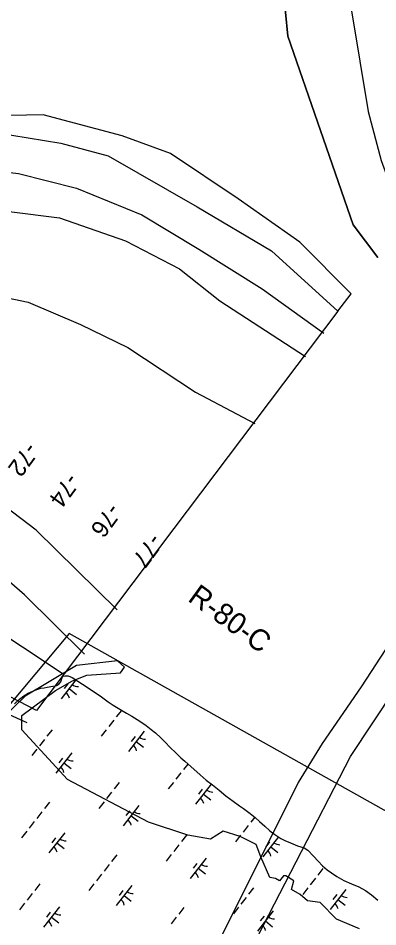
# Model space of a CAD drawing. Extents: x 3896831 to 3918110, y 171006 to 193349.
# Drawn here: x 3907102 to 3907802, y 176349 to 178119 of the extents above; entities that cross this region are included whole.
import ezdxf

# ---------------------------------------------------------------- set-up
doc = ezdxf.new("R2010")
doc.units = 0
for name, color, linetype in [('V-RIVR-EDGE', 7, 'Continuous'), ('V-RIVR-RANG', 7, 'Continuous'), ('V-RIVR-RANG-IDEN', 7, 'Continuous'), ('V-RRAP-FSHR', 7, 'Continuous'), ('V-TOPO-DPTH', 7, 'Continuous'), ('V-TOPO-MAJR', 7, 'Continuous'), ('V-TOPO-MINR', 7, 'Continuous'), ('V-UTIL-LINE', 7, 'Continuous'), ('V-WETL-SWMP', 7, 'Continuous')]:
    doc.layers.add(name, color=color, linetype=linetype)

msp = doc.modelspace()

# ---------------------------------------------------------------- linework, layer by layer
at = {"layer": 'V-RIVR-EDGE'}
msp.add_lwpolyline([(3907767, 176345.3), (3907721.7, 176364), (3907690.4, 176396.8), (3907665.4, 176400), (3907651.4, 176412.5), (3907634.2, 176421.8), (3907638.9, 176439), (3907623.2, 176448.4), (3907618.5, 176448.4), (3907610.7, 176439), (3907602.9, 176443.7), (3907592, 176445.3), (3907574.8, 176485.9), (3907565.4, 176509.4), (3907534.1, 176525), (3907501.3, 176535.9), (3907476.3, 176520.3), (3907432.5, 176528.1), (3907355.9, 176553.1), (3907198.1, 176636), (3907109, 176732.9), (3907109, 176761), (3907174.6, 176809.5), (3907207.4, 176828.2), (3907235.6, 176839.2), (3907301.2, 176843.9), (3907309, 176854.8), (3907295, 176867.3), (3907215.3, 176857.9), (3907115.2, 176798.5), (3907038.6, 176725.1)], dxfattribs=at)
at = {"layer": 'V-RRAP-FSHR'}
msp.add_lwpolyline([(3908001.4, 176472.2), (3907201.3, 176920.5), (3906173.6, 175695), (3905294, 175071.7), (3904787.4, 174237.7)], dxfattribs=at)
at = {"layer": 'V-TOPO-DPTH'}
for q in [(3907750.4, 177581.8), (3907137.2, 176770.5)]:
    msp.add_line((3907724.8, 177547.9), q, dxfattribs=at)
for points in [[(3907802.4, 177652.7), (3907754.6, 177716.3), (3907627.2, 178083.7), (3907599.9, 178364.7), (3907615.4, 178532.3), (3907646.9, 178623.4), (3907701.3, 178701.9)], [(3907701.3, 178701.9), (3907646.9, 178623.4), (3907615.4, 178532.3), (3907599.9, 178364.7), (3907627.2, 178083.7), (3907754.6, 177716.3), (3907802.4, 177652.7)], [(3907750.4, 177581.8), (3907650.6, 177682.4), (3907530.5, 177766.6), (3907398.8, 177854.9), (3907304.2, 177889.3), (3907150.4, 177930.5), (3907051.9, 177928.3)], [(3907750.4, 177581.8), (3907650.6, 177682.4), (3907530.5, 177766.6), (3907398.8, 177854.9), (3907304.2, 177889.3), (3907150.4, 177930.5), (3907051.9, 177928.3)], [(3907137.2, 176770.5), (3907017.8, 176832.2), (3906783.3, 176956), (3906642.5, 177046.4), (3906576.4, 177130.2), (3906534.8, 177214.7), (3906507.5, 177292), (3906536, 177389.4), (3906584, 177547.5), (3906616.4, 177594), (3906701.7, 177702.8), (3906783.4, 177786.6), (3906899.5, 177863.4), (3907056.7, 177895.9), (3907184.6, 177875.5), (3907277.1, 177850.9), (3907450.4, 177751.1), (3907595.1, 177665.6), (3907724.8, 177547.9)], [(3907137.2, 176770.5), (3907017.8, 176832.2), (3906783.3, 176956), (3906642.5, 177046.4), (3906576.4, 177130.2), (3906534.8, 177214.7), (3906507.5, 177292), (3906536, 177389.4), (3906584, 177547.5), (3906616.4, 177594), (3906701.7, 177702.8), (3906783.4, 177786.6), (3906899.5, 177863.4), (3907056.7, 177895.9), (3907184.6, 177875.5), (3907277.1, 177850.9), (3907450.4, 177751.1), (3907595.1, 177665.6), (3907724.8, 177547.9)], [(3907037.7, 176783.3), (3907118.6, 176747.2), (3907118.6, 176747.2), (3907118.6, 176747.2)], [(3907037.7, 176783.3), (3907118.6, 176747.2), (3907118.6, 176747.2), (3907118.6, 176747.2)]]:
    msp.add_lwpolyline(points, dxfattribs=at)
at = {"layer": 'V-TOPO-MAJR'}
msp.add_lwpolyline([(3907191.5, 176839.8), (3907028.4, 176947.6), (3906922, 177031), (3906808.2, 177120.2), (3906707.1, 177215.4), (3906631.8, 177282.4), (3906605.8, 177330.7), (3906587.8, 177368.9), (3906582.7, 177428.7), (3906610, 177499.2), (3906694.4, 177652.7), (3906753.3, 177702.4), (3906826.8, 177760.5), (3906911.4, 177802.1), (3906999.9, 177828.5), (3907102.2, 177816.3), (3907215.4, 177787.5), (3907342.6, 177735.7), (3907453.7, 177668.6), (3907577.2, 177591.8), (3907697.3, 177505.3)], dxfattribs=at)
at = {"layer": 'V-TOPO-MINR'}
for points in [[(3907701.3, 178701.9), (3907646.9, 178623.4), (3907615.4, 178532.3), (3907599.9, 178364.7), (3907627.2, 178083.7), (3907754.6, 177716.3), (3907802.4, 177652.7)], [(3907786.2, 178645.6), (3907752, 178569), (3907730.7, 178485.8), (3907721.7, 178357.1), (3907734.2, 178235.5), (3907783.8, 177937), (3907808.8, 177841.5), (3907835.6, 177768.6), (3907857.3, 177732.9)], [(3907750.4, 177581.8), (3907650.6, 177682.4), (3907530.5, 177766.6), (3907398.8, 177854.9), (3907304.2, 177889.3), (3907150.4, 177930.5), (3907051.9, 177928.3)], [(3907137.2, 176770.5), (3907017.8, 176832.2), (3906783.3, 176956), (3906642.5, 177046.4), (3906576.4, 177130.2), (3906534.8, 177214.7), (3906507.5, 177292), (3906536, 177389.4), (3906584, 177547.5), (3906616.4, 177594), (3906701.7, 177702.8), (3906783.4, 177786.6), (3906899.5, 177863.4), (3907056.7, 177895.9), (3907184.6, 177875.5), (3907277.1, 177850.9), (3907450.4, 177751.1), (3907595.1, 177665.6), (3907724.8, 177547.9)], [(3907231.3, 176880.4), (3907114.3, 176996.1), (3906997, 177096.1), (3906889.5, 177188.3), (3906684.2, 177349.2), (3906647.9, 177389.6), (3906632, 177410), (3906633.9, 177468.5), (3906687.8, 177578), (3906718.3, 177622), (3906750.7, 177668.5), (3906804.8, 177701.9), (3906892.9, 177732.7), (3906991.1, 177735.7), (3907084.3, 177742.5), (3907182.1, 177729.7), (3907310.7, 177684.9), (3907415.8, 177630.4), (3907494.9, 177568.4), (3907661.6, 177459.9)], [(3907294.8, 176966.5), (3907137.1, 177122), (3907016.4, 177212.6), (3906947.5, 177282.6), (3906881, 177350.7), (3906837.3, 177396.9), (3906829, 177447.4), (3906871.1, 177506.2), (3906934.4, 177556.4), (3906996, 177584), (3907052.5, 177579.7), (3907121.4, 177565.6), (3907222.9, 177522), (3907315.7, 177477.2), (3907447.1, 177390.2), (3907563.1, 177329.3)], [(3907037.7, 176783.3), (3907118.6, 176747.2), (3907118.6, 176747.2), (3907118.6, 176747.2)]]:
    msp.add_lwpolyline(points, dxfattribs=at)
at = {"layer": 'V-UTIL-LINE'}
for points in [[(3905549.4, 173652.6), (3906763.3, 174938.4), (3906949.5, 175133), (3906970.6, 175166.8), (3907325.9, 175860.5), (3907748.9, 176681), (3908142.2, 177273.2), (3908679.4, 178098), (3908869.7, 178381.4), (3908937.4, 178537.8), (3909170, 179117.3), (3909533.8, 179633.3), (3910092.1, 180424.3), (3910333.2, 180766.9), (3910760.4, 181291.4), (3910921.1, 181524), (3911225.6, 181951.2), (3911822, 182788.6), (3911961.6, 182987.4), (3912147.7, 183114.3), (3912722.9, 183841.8), (3913090.9, 184307.1), (3913848, 185258.8), (3914364, 185910.1)], [(3913133.2, 183520.4), (3913116.3, 183516.1), (3912989.4, 183516.1), (3912744.1, 183393.5), (3911902.4, 182441.8), (3910866.1, 181249.1), (3910603.9, 180953), (3910214.7, 180504.6), (3910138.6, 180390.4), (3909757.9, 179819.4), (3909457.6, 179366.9), (3909009.3, 178685.9), (3908785.1, 178351.7), (3908150.7, 177400.1), (3907770, 176816.4), (3907693.9, 176706.4), (3907647.3, 176630.3), (3907300.5, 175936.6), (3907025.6, 175369.8), (3906945.2, 175204.9), (3906416.5, 174650.8), (3905507.1, 173682.2)]]:
    msp.add_lwpolyline(points, dxfattribs=at)
at = {"layer": 'V-WETL-SWMP'}
for p, q in [((3907184.6, 176826.5), (3907187.6, 176835.1)), ((3907187.6, 176835.1), (3907188.7, 176836.9)), ((3907188.7, 176836.9), (3907188.9, 176837.1)), ((3907188.9, 176837.1), (3907193.6, 176838.2)), ((3907193.6, 176838.2), (3907199, 176838)), ((3907199, 176838), (3907206.8, 176834.9)), ((3907206.8, 176834.9), (3907226.8, 176821.9)), ((3907158.5, 176816), (3907169.6, 176817.8)), ((3907169.6, 176817.8), (3907176.6, 176819.2)), ((3907176.6, 176819.2), (3907181.5, 176822.6)), ((3907181.5, 176822.6), (3907184.6, 176826.5)), ((3907214.3, 176830), (3907185.6, 176793.4)), ((3907198.6, 176822.5), (3907191.2, 176813.1)), ((3907226.8, 176821.9), (3907253.7, 176804.4)), ((3907104.6, 176792.5), (3907113.1, 176799.3)), ((3907113.1, 176799.3), (3907121.3, 176804)), ((3907121.3, 176804), (3907130.3, 176808)), ((3907130.3, 176808), (3907139.9, 176811.9)), ((3907139.9, 176811.9), (3907146.1, 176813.8)), ((3907146.1, 176813.8), (3907152.1, 176814.9)), ((3907152.1, 176814.9), (3907158.5, 176816)), ((3907201, 176813.1), (3907215.2, 176802)), ((3907253.7, 176804.4), (3907264.4, 176796.9)), ((3907094.5, 176783.7), (3907104.6, 176792.5)), ((3907264.4, 176796.9), (3907276.9, 176787.6)), ((3907276.9, 176787.6), (3907286.6, 176781.2)), ((3907286.6, 176781.2), (3907299.7, 176773.2)), ((3907302.8, 176770.6), (3907293, 176758.1)), ((3907299.7, 176773.2), (3907313, 176765.5)), ((3907313, 176765.5), (3907322.9, 176759.6)), ((3907288, 176751.8), (3907278.2, 176739.2)), ((3907322.9, 176759.6), (3907333.4, 176752.9)), ((3907333.4, 176752.9), (3907342.8, 176747)), ((3907342.8, 176747), (3907350.9, 176741.6)), ((3907167.8, 176733), (3907157.9, 176720.4)), ((3907273.2, 176732.9), (3907263.3, 176720.3)), ((3907347.4, 176730.1), (3907316.5, 176690.8)), ((3907350.9, 176741.6), (3907361.1, 176733.6)), ((3907361.1, 176733.6), (3907369.2, 176726.8)), ((3907153, 176714.1), (3907143.1, 176701.5)), ((3907329.6, 176719.9), (3907322.2, 176710.5)), ((3907331.9, 176710.5), (3907346.1, 176699.4)), ((3907369.2, 176726.8), (3907380, 176717.3)), ((3907380, 176717.3), (3907388.4, 176709)), ((3907138.1, 176695.2), (3907128.3, 176682.6)), ((3907388.4, 176709), (3907397.8, 176698.7)), ((3907397.8, 176698.7), (3907408.8, 176687.8)), ((3907206, 176688.2), (3907175.1, 176648.8)), ((3907188.2, 176678), (3907180.8, 176668.5)), ((3907408.8, 176687.8), (3907418.8, 176678.5)), ((3907418.8, 176678.5), (3907426.4, 176671.8)), ((3907190.5, 176668.5), (3907204.7, 176657.4)), ((3907432.4, 176666.3), (3907423.9, 176655.4)), ((3907426.4, 176671.8), (3907432.7, 176666.1)), ((3907432.7, 176666.1), (3907443.7, 176656.6)), ((3907418.9, 176649.1), (3907409.1, 176636.6)), ((3907443.7, 176656.6), (3907456.2, 176645.5)), ((3907456.2, 176645.5), (3907468.3, 176635.1)), ((3907298.7, 176630.4), (3907288.8, 176617.8)), ((3907404.1, 176630.3), (3907394.3, 176617.7)), ((3907478, 176627.2), (3907447.4, 176588.2)), ((3907468.3, 176635.1), (3907480.1, 176625.6)), ((3907480.1, 176625.6), (3907493.1, 176615.3)), ((3907283.9, 176611.5), (3907274, 176598.9)), ((3907460.5, 176617.3), (3907453.1, 176607.9)), ((3907462.8, 176607.8), (3907477, 176596.7)), ((3907493.1, 176615.3), (3907506.2, 176604.7)), ((3907506.2, 176604.7), (3907520.4, 176593.8)), ((3907162.8, 176592), (3907153, 176579.4)), ((3907269.1, 176592.6), (3907259.2, 176580)), ((3907520.4, 176593.8), (3907533.2, 176585.1)), ((3907148, 176573.1), (3907138.2, 176560.5)), ((3907336.9, 176585.6), (3907306, 176546.2)), ((3907319.1, 176575.4), (3907311.7, 176565.9)), ((3907533.2, 176585.1), (3907540.8, 176579.4)), ((3907540.8, 176579.4), (3907553.8, 176570.1)), ((3907553.8, 176570.1), (3907563.3, 176562.1)), ((3907133.2, 176554.2), (3907123.3, 176541.6)), ((3907321.5, 176565.9), (3907335.6, 176554.8)), ((3907562.6, 176562.7), (3907554.8, 176552.8)), ((3907563.3, 176562.1), (3907572.2, 176554.4)), ((3907572.2, 176554.4), (3907582.1, 176545.1)), ((3907118.4, 176535.4), (3907108.5, 176522.8)), ((3907549.9, 176546.5), (3907540, 176533.9)), ((3907582.1, 176545.1), (3907592.3, 176536.3)), ((3907592.3, 176536.3), (3907601.5, 176528.8)), ((3907192.5, 176532.6), (3907161.7, 176493.3)), ((3907174.8, 176522.4), (3907167.4, 176513)), ((3907429.6, 176527.8), (3907419.7, 176515.2)), ((3907535.1, 176527.7), (3907525.2, 176515.1)), ((3907608.7, 176524.3), (3907578.3, 176485.6)), ((3907601.5, 176528.8), (3907613.3, 176521.4)), ((3907613.3, 176521.4), (3907621.4, 176517.5)), ((3907621.4, 176517.5), (3907632.1, 176512.9)), ((3907177.1, 176512.9), (3907191.3, 176501.8)), ((3907414.8, 176508.9), (3907404.9, 176496.3)), ((3907591.4, 176514.7), (3907584, 176505.3)), ((3907593.8, 176505.2), (3907607.9, 176494.1)), ((3907632.1, 176512.9), (3907646.2, 176507.3)), ((3907646.2, 176507.3), (3907652.7, 176505.2)), ((3907652.7, 176505.2), (3907658.7, 176503.2)), ((3907658.7, 176503.2), (3907666.3, 176498.3)), ((3907666.3, 176498.3), (3907677, 176487.2)), ((3907293.7, 176489.4), (3907283.9, 176476.8)), ((3907400, 176490), (3907390.1, 176477.4)), ((3907467.8, 176483), (3907437, 176443.6)), ((3907677, 176487.2), (3907686.5, 176477.4)), ((3907278.9, 176470.5), (3907269.1, 176457.9)), ((3907450, 176472.8), (3907442.6, 176463.3)), ((3907452.4, 176463.3), (3907466.5, 176452.2)), ((3907695.6, 176462.8), (3907685.7, 176450.2)), ((3907686.5, 176477.4), (3907694.8, 176468)), ((3907694.8, 176468), (3907703.5, 176460.6)), ((3907264.1, 176451.6), (3907254.3, 176439)), ((3907703.5, 176460.6), (3907711.9, 176454.6)), ((3907711.9, 176454.6), (3907722.8, 176447.4)), ((3907722.8, 176447.4), (3907736.2, 176439.7)), ((3907143.9, 176432.9), (3907134, 176420.3)), ((3907249.3, 176432.7), (3907239.5, 176420.1)), ((3907323.5, 176430), (3907292.6, 176390.7)), ((3907680.8, 176443.9), (3907670.9, 176431.3)), ((3907736.2, 176439.7), (3907751.3, 176433.3)), ((3907751.3, 176433.3), (3907765.4, 176427.1)), ((3907765.4, 176427.1), (3907778.5, 176419.9)), ((3907129.1, 176414), (3907119.2, 176401.4)), ((3907305.7, 176419.8), (3907298.3, 176410.4)), ((3907308, 176410.3), (3907322.2, 176399.2)), ((3907560.5, 176425.2), (3907550.6, 176412.6)), ((3907666, 176425), (3907656.1, 176412.4)), ((3907740.1, 176422.3), (3907709.3, 176383)), ((3907722.3, 176412.1), (3907714.9, 176402.7)), ((3907778.5, 176419.9), (3907790.2, 176411.4)), ((3907790.2, 176411.4), (3907802.6, 176401.1)), ((3907114.3, 176395.1), (3907104.4, 176382.5)), ((3907545.7, 176406.3), (3907535.8, 176393.7)), ((3907724.7, 176402.6), (3907738.9, 176391.5)), ((3907182.1, 176388.1), (3907151.2, 176348.7)), ((3907164.3, 176377.9), (3907156.9, 176368.4)), ((3907424.7, 176386.8), (3907414.8, 176374.2)), ((3907530.9, 176387.4), (3907521, 176374.8)), ((3907598.7, 176380.4), (3907567.9, 176341)), ((3907166.7, 176368.4), (3907180.8, 176357.3)), ((3907409.9, 176367.9), (3907400, 176355.3)), ((3907580.9, 176370.2), (3907573.5, 176360.7)), ((3907583.3, 176360.7), (3907597.5, 176349.6))]:
    msp.add_line(p, q, dxfattribs=at)
for centre, start, end in [((3907218.2, 176834.7), 231.1403, 272.6839), ((3907184.2, 176791.2), 11.1403, 52.6839), ((3907349.2, 176732.1), 231.1403, 272.6839), ((3907315.1, 176688.6), 11.1403, 52.6839), ((3907207.8, 176690.1), 231.1403, 272.6839), ((3907173.7, 176646.6), 11.1403, 52.6839), ((3907480.1, 176629.4), 231.1403, 272.6839), ((3907446, 176586), 11.1403, 52.6839), ((3907338.7, 176587.5), 231.1403, 272.6839), ((3907304.6, 176544), 11.1403, 52.6839), ((3907194.3, 176534.5), 231.1403, 272.6839), ((3907160.3, 176491.1), 11.1403, 52.6839), ((3907611, 176526.8), 231.1403, 272.6839), ((3907576.9, 176483.4), 11.1403, 52.6839), ((3907469.6, 176484.9), 231.1403, 272.6839), ((3907435.5, 176441.4), 11.1403, 52.6839), ((3907325.3, 176431.9), 231.1403, 272.6839), ((3907741.9, 176424.2), 231.1403, 272.6839), ((3907291.2, 176388.4), 11.1403, 52.6839), ((3907707.8, 176380.7), 11.1403, 52.6839), ((3907183.9, 176390), 231.1403, 272.6839), ((3907149.8, 176346.5), 11.1403, 52.6839), ((3907600.5, 176382.3), 231.1403, 272.6839), ((3907566.4, 176338.8), 11.1403, 52.6839)]:
    msp.add_arc(centre, 17.6, start, end, dxfattribs=at)

# ---------------------------------------------------------------- texts
at = {"layer": 'V-RIVR-RANG'}
for s, p in [('-72', (3907118.4, 177294.8)), ('-74', (3907198.4, 177234.9)), ('-76', (3907279.4, 177176.2)), ('-77', (3907360.4, 177117.5))]:
    msp.add_text(s, height=33.5, rotation=233.8883, dxfattribs=at).set_placement(p)
at = {"layer": 'V-RIVR-RANG-IDEN'}
msp.add_text('R-80-C', height=41.5, rotation=324.0315, dxfattribs=at).set_placement((3907430.2, 176985.3))

doc.saveas('drawing.dxf')
